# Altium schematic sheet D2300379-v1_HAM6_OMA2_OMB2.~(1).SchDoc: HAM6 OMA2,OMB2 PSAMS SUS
size C; Engineer: L. Sanchez; Organization: LIGO Laboratory; Address1: California Institute of Technology; Address2: Massachusetts Institute of Technology; DocumentNumber: D2300379; Revision: v1; SheetNumber: 3; SheetTotal: 9
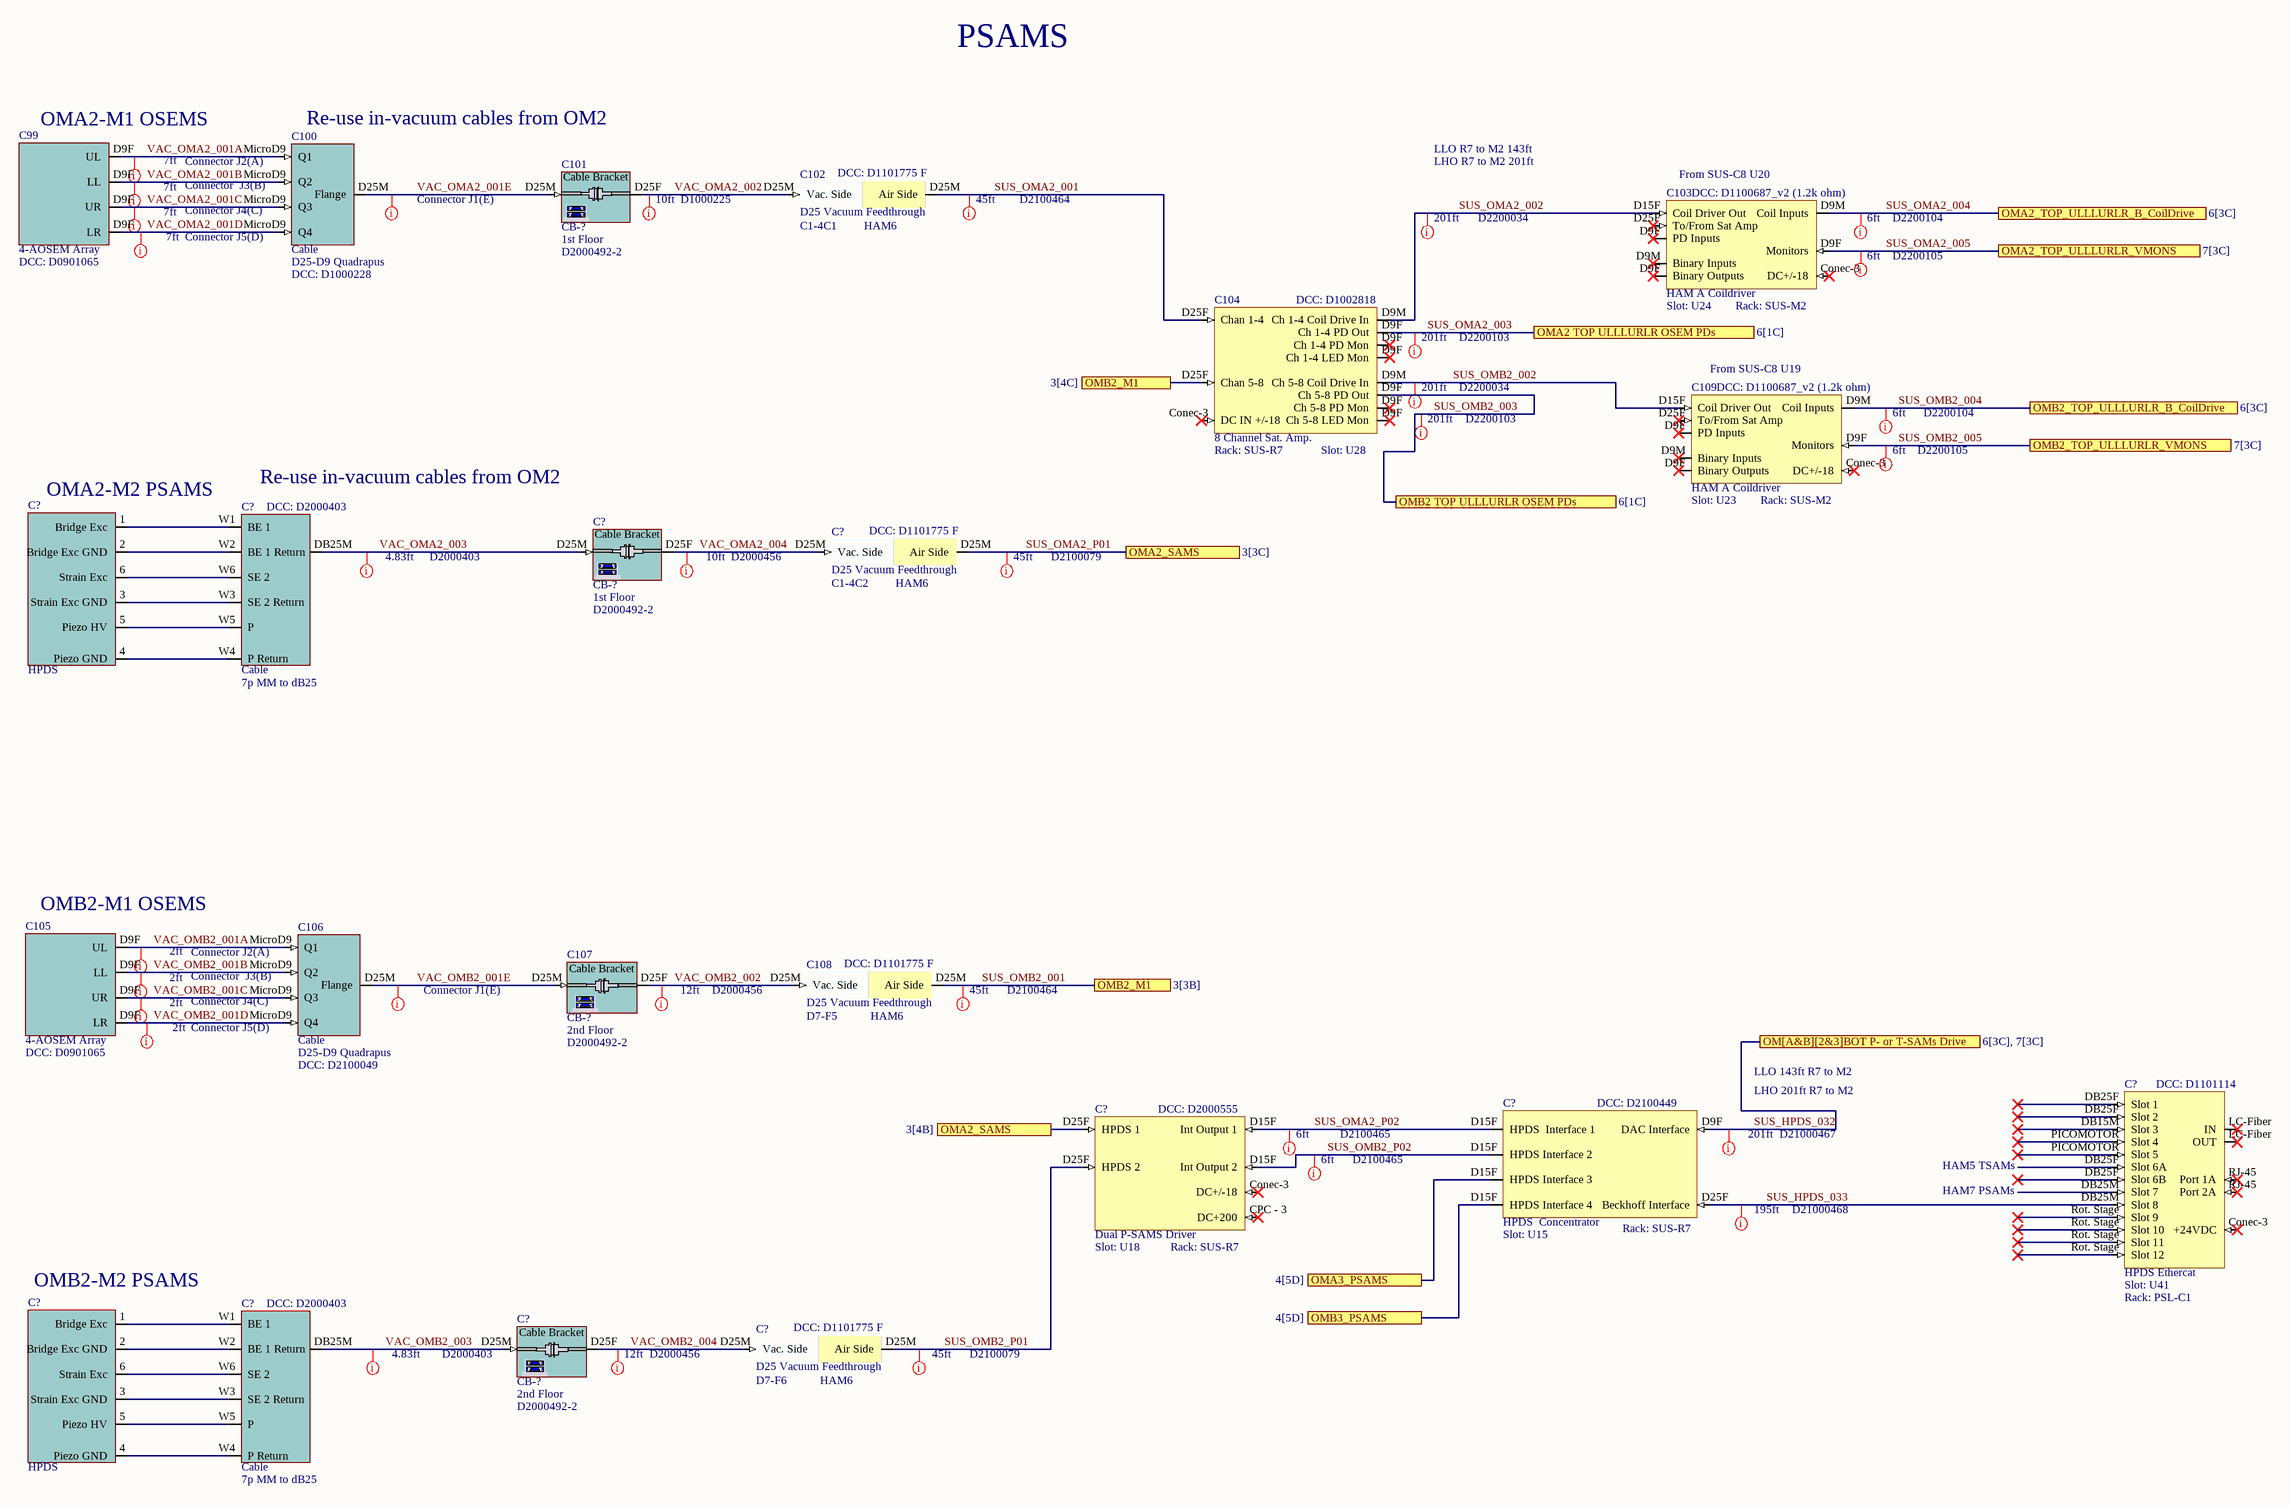
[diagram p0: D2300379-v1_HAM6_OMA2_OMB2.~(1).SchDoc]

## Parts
(Parts that share a designator on the sheet are numbered #1, #2 ... from top to bottom, then left to right.)
C99  4-AOSEM Array  DCC: D0901065
C100  Cable  value D25-D9 Quadrapus  DCC: D1000228
C101  Rack: CB-?  Slot: 1st Floor  DCC: D2000492-2  (hidden comment: Cable Bracket)
C102  D25 Vacuum Feedthrough  DCC: D1101775 F  Feedthrough: C1-4C1  Chamber: HAM6
C103  HAM A Coildriver  DCC: D1100687_v2 (1.2k ohm)  Rack: SUS-M2  Slot: U24
C104  8 Channel Sat. Amp.  DCC: D1002818  Rack: SUS-R7  Slot: U28
C105  4-AOSEM Array  DCC: D0901065
C106  Cable  value D25-D9 Quadrapus  DCC: D2100049
C107  Rack: CB-?  Slot: 2nd Floor  DCC: D2000492-2  (hidden comment: Cable Bracket)
C108  D25 Vacuum Feedthrough  DCC: D1101775 F  Feedthrough: D7-F5  Chamber: HAM6
C109  HAM A Coildriver  DCC: D1100687_v2 (1.2k ohm)  Rack: SUS-M2  Slot: U23
C?#1  Rack: CB-?  Slot: 1st Floor  DCC: D2000492-2  (hidden comment: Cable Bracket)
C?#2  D25 Vacuum Feedthrough  DCC: D1101775 F  Feedthrough: C1-4C2  Chamber: HAM6
C?#3  Cable  value 7p MM to dB25  DCC: D2000403
C?#4  HPDS
C?#5  HPDS  Concentrator  Slot: U15  Rack: SUS-R7  DCC: D2100449
C?#6  Dual P-SAMS Driver  Slot: U18  Rack: SUS-R7  DCC: D2000555
C?#7  HPDS Ethercat  Slot: U41  Rack: PSL-C1  DCC: D1101114
C?#8  Rack: CB-?  Slot: 2nd Floor  DCC: D2000492-2  (hidden comment: Cable Bracket)
C?#9  D25 Vacuum Feedthrough  DCC: D1101775 F  Feedthrough: D7-F6  Chamber: HAM6
C?#10  Cable  value 7p MM to dB25  DCC: D2000403
C?#11  HPDS

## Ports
OM[A&B][2&3]BOT P- or T-SAMs Drive (see 6[3C], 7[3C]), OMA2 TOP ULLLURLR OSEM PDs (see 6[1C]), OMA2_SAMS (see 3[3C]), OMA2_SAMS (see 3[4B]), OMA2_TOP_ULLLURLR_B_CoilDrive (see 6[3C]), OMA2_TOP_ULLLURLR_VMONS (see 7[3C]), OMA3_PSAMS (see 4[5D]), OMB2 TOP ULLLURLR OSEM PDs (see 6[1C]), OMB2_M1 (see 3[3B]), OMB2_M1 (see 3[4C]), OMB2_TOP_ULLLURLR_B_CoilDrive (see 6[3C]), OMB2_TOP_ULLLURLR_VMONS (see 7[3C]), OMB3_PSAMS (see 4[5D])

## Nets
OMA3_PSAMS: C?#5.D15F(HPDS_Interface_3) ; port OMA3_PSAMS
OMB3_PSAMS: C?#5.D15F(HPDS_Interface_4) ; port OMB3_PSAMS
SUS_HPDS_032: C?#5.D9F(DAC_Interface) ; port OM[A&B][2&3]BOT P- or T-SAMs Drive
SUS_HPDS_033: C?#5.D25F(Beckhoff_Interface) C?#7.DB25M(Slot_8)
SUS_OMA2_001: C102.D25M(Air_Side) C104.D25F(Chan_1-4)
SUS_OMA2_002: C103.D15F(Coil_Driver_Out) C104.D9M(Ch_1-4_Coil_Drive_In)
SUS_OMA2_003: C104.D9F(Ch_1-4_PD_Out) ; port OMA2 TOP ULLLURLR OSEM PDs
SUS_OMA2_004: C103.D9M(Coil_Inputs) ; port OMA2_TOP_ULLLURLR_B_CoilDrive
SUS_OMA2_005: C103.D9F(PD_Inputs) ; port OMA2_TOP_ULLLURLR_VMONS
SUS_OMA2_P01: C?#2.D25M(Air_Side) C?#6.D25F(HPDS_1) ; port OMA2_SAMS
SUS_OMA2_P02: C?#5.D15F(HPDS__Interface_1) C?#6.D15F(Int_Output_1)
SUS_OMB2_001: C104.D25F(Chan_5-8) C108.D25M(Air_Side) ; port OMB2_M1
SUS_OMB2_002: C104.D9M(Ch_5-8_Coil_Drive_In) C109.D15F(Coil_Driver_Out)
SUS_OMB2_003: C104.D9F(Ch_5-8_PD_Out) ; port OMB2 TOP ULLLURLR OSEM PDs
SUS_OMB2_004: C109.D9M(Coil_Inputs) ; port OMB2_TOP_ULLLURLR_B_CoilDrive
SUS_OMB2_005: C109.D9F(PD_Inputs) ; port OMB2_TOP_ULLLURLR_VMONS
SUS_OMB2_P01: C?#6.D25F(HPDS_2) C?#9.D25M(Air_Side)
SUS_OMB2_P02: C?#5.D15F(HPDS_Interface_2) C?#6.D15F(Int_Output_2)
VAC_OMA2_001A: C99.D9F(UL) C100.MicroD9(Q1)
VAC_OMA2_001B: C99.D9F(LL) C100.MicroD9(Q2)
VAC_OMA2_001C: C99.D9F(UR) C100.MicroD9(Q3)
VAC_OMA2_001D: C99.D9F(LR) C100.MicroD9(Q4)
VAC_OMA2_001E: C100.D25M(Flange) C101.D25M
VAC_OMA2_002: C101.D25F C102.D25M(Vac._Side)
VAC_OMA2_003: C?#1.D25M C?#3.DB25M
VAC_OMA2_004: C?#1.D25F C?#2.D25M(Vac._Side)
VAC_OMB2_001A: C105.D9F(UL) C106.MicroD9(Q1)
VAC_OMB2_001B: C105.D9F(LL) C106.MicroD9(Q2)
VAC_OMB2_001C: C105.D9F(UR) C106.MicroD9(Q3)
VAC_OMB2_001D: C105.D9F(LR) C106.MicroD9(Q4)
VAC_OMB2_001E: C106.D25M(Flange) C107.D25M
VAC_OMB2_002: C107.D25F C108.D25M(Vac._Side)
VAC_OMB2_003: C?#8.D25M C?#10.DB25M
VAC_OMB2_004: C?#8.D25F C?#9.D25M(Vac._Side)
NetC?#3_W1: C?#3.W1(BE_1) C?#4.1(Bridge_Exc)
NetC?#3_W2: C?#3.W2(BE_1_Return) C?#4.2(Bridge_Exc_GND)
NetC?#3_W3: C?#3.W3(SE_2_Return) C?#4.3(Strain_Exc_GND)
NetC?#3_W4: C?#3.W4(P_Return) C?#4.4(Piezo_GND)
NetC?#3_W5: C?#3.W5(P) C?#4.5(Piezo_HV)
NetC?#3_W6: C?#3.W6(SE_2) C?#4.6(Strain_Exc)
NetC?#10_W1: C?#10.W1(BE_1) C?#11.1(Bridge_Exc)
NetC?#10_W2: C?#10.W2(BE_1_Return) C?#11.2(Bridge_Exc_GND)
NetC?#10_W3: C?#10.W3(SE_2_Return) C?#11.3(Strain_Exc_GND)
NetC?#10_W4: C?#10.W4(P_Return) C?#11.4(Piezo_GND)
NetC?#10_W5: C?#10.W5(P) C?#11.5(Piezo_HV)
NetC?#10_W6: C?#10.W6(SE_2) C?#11.6(Strain_Exc)

Not connected (* = marked no-connect by the designer): C103 Conec-3(DC+/-18)* D25F(To/From_Sat_Amp)*; C104 Conec-3(DC_IN_+/-18)*; C109 Conec-3(DC+/-18)* D25F(To/From_Sat_Amp)*; C?#6 Conec-3(DC+/-18)* CPC - 3(DC+200)*; C?#7 Conec-3(+24VDC)* DB15M(Slot_3)* DB25F(Slot_1)* LC-Fiber(IN)* PICOMOTOR(Slot_4)* RJ-45(Port_1A)* Rot. Stage(Slot_9)*

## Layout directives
Length: 7ft; DCC: Connector J5(D): VAC_OMA2_001D
Length: 7ft; DCC: Connector J2(A): VAC_OMA2_001A
Length: 7ft; DCC: Connector  J3(B): VAC_OMA2_001B
Length: 7ft; DCC: Connector J4(C): VAC_OMA2_001C
Length: 2ft; DCC: Connector J5(D): VAC_OMB2_001D
Length: 2ft; DCC: Connector J2(A): VAC_OMB2_001A
Length: 2ft; DCC: Connector  J3(B): VAC_OMB2_001B
Length: 2ft; DCC: Connector J4(C): VAC_OMB2_001C
Length: 10ft; DCC: D1000225: VAC_OMA2_002
Length: 12ft; DCC: D2000456: VAC_OMB2_002, VAC_OMB2_004
Length: 5; DCC: Connector J1(E): VAC_OMA2_001E, VAC_OMB2_001E
Length: 201ft; DCC: D2200103: SUS_OMA2_003, SUS_OMB2_003
Length: 201ft; DCC: D2200034: SUS_OMA2_002, SUS_OMB2_002
Length: 6ft; DCC: D2200104: SUS_OMA2_004, SUS_OMB2_004
Length: 6ft; DCC: D2200105: SUS_OMA2_005, SUS_OMB2_005
Length: 45ft; DCC: D2100464: SUS_OMA2_001, SUS_OMB2_001
Length: 45ft; DCC: D2100079: SUS_OMA2_P01, SUS_OMB2_P01
Length: 10ft; DCC: D2000456: VAC_OMA2_004
Length: 4.83ft; DCC: D2000403: VAC_OMA2_003, VAC_OMB2_003
Length: 195ft; DCC: D21000468: SUS_HPDS_033
Length: 201ft; DCC: D21000467: SUS_HPDS_032
Length: 6ft; DCC: D2100465: SUS_OMA2_P02, SUS_OMB2_P02

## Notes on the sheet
- PSAMS
- (near C99) OMA2-M1 OSEMS
- (near C100) Re-use in-vacuum cables from OM2
- LLO R7 to M2 143ft
- LHO R7 to M2 201ft
- (near C103) From SUS-C8 U20
- (near C109) From SUS-C8 U19
- (near C?#4) OMA2-M2 PSAMS
- (near C?#3) Re-use in-vacuum cables from OM2
- (near C105) OMB2-M1 OSEMS
- LLO 143ft R7 to M2
- LHO 201ft R7 to M2
- HAM7 PSAMs
- HAM5 TSAMs
- (near C?#11) OMB2-M2 PSAMS

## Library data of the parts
C99 = 4-BOSEM Array: Rack: SUS-R?; Serial: Sxxxxxxx; Slot: U?; System: SUS; Parameter: OMA1 HAM6 M1
C100 C106 = Flange: Rack: SUS-R?; Serial: Sxxxxxxx; Slot: U?; System: SUS
C101 C?#1 = D1001347-2 1st Cable Bracket: D1001347-2 1/2 Cable Bracket for BSC Tables; Serial: Sxxxxxxx; System: SUS
C102 C108 C?#2 C?#9 = VacFeedD25: Serial: Sxxxxxxx; System: ISC; Rack: R?; Slot: U?
C103 C109 = HAM A Coildriver: Serial: Sxxxxxxx; System: ISC
C104 = 8 Channel Sat. Amp.: Serial: Sxxxxxxx; System: ISC
C105 = 4-BOSEM Array: Rack: SUS-R?; Serial: Sxxxxxxx; Slot: U?; System: SUS; Parameter: OMB1 HAM6 M1
C107 C?#8 = D1001347-2 2nd Cable Bracket: D1001347-2 2/2 Cable Bracket for BSC Tables; Serial: Sxxxxxxx; System: SUS
C?#3 C?#10 = MM Piezo: Piezo or Thermal; Rack: SUS-R?; Serial: Sxxxxxxx; Slot?: U?; System: SUS
C?#4 C?#11 = HDS+Piezo: HAM Double Suspension with Piezo Driver
C?#5 = HPDS Concentrator: Serial: S?; System: SUS
C?#6 = Dual P-SAMS: Strain Gauge and PZT Driver; Serial: Sxxxxxxx; System: SUS
C?#7 = HPDS Ethercat: PSL - C1; System: MISC; Serial: Sxxxxxxx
